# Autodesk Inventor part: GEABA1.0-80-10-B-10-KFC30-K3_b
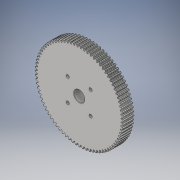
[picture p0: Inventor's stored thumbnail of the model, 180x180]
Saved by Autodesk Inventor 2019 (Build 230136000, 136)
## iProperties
Created: 2022-11
Part Number: GEABA1.0-80-10-B-10-KFC30-K3_b
Material: Generic
Catalog Web Link: www.cadenas.de
Description: GEABM, GEABMS, GEABMT, GEABP, GEABPS, GEABPT, GEABA, GEABAS, GEABAT_body-Plastic Spur Gears - Pressure Angle 20 Degrees, Module 0.5/0.8/1.0/1.5/2.0/2.5/3.0
Vendor: MISUMI
Document SubType Name: Modeling
Designer: psAdmin
Manufacturer: MISUMI
Mass: 60.3274 g
Surface Area: 174.386 cm^2
Volume: 60.3274 cm^3
Density: 1 g/cm^3
Appearance: PSOLRGB-175-175-175
Category: PARTsolutions
Company: MISUMI
Title: GEABA1.0-80-10-B-10-KFC30-K3
Author: Cadenas PARTsolutions
Comments: Plastic Spur Gears - Pressure Angle 20 Degrees, Module 0.5/0.8/1.0/1.5/2.0/2.5/3.0
PSOL_IDENT_0: {$CADENAS_DATA/23d-libs/misumi/metric/54_spur_gears/geabms20/geabms20.prj},408 {VTYP=3D},{NB=GEABA1.
PSOL_IDENT_1: 0-80-10-B-10-KFC30-K3_b},{LINA=GEABA1.0-80-10-B-10-KFC30-K3},{NN=GEABM, GEABMS, GEABMT, GEABP, GEABP
PSOL_IDENT_2: S, GEABPT, GEABA, GEABAS, GEABAT_body},{DATE=17.10.2022 23:48:33},{GEOMDATE=14.09.2022 05:11:00},{VE
PSOL_IDENT_3: RSION=},{LINEID=30},{WBVAR=MATSG,MATCR,NT,B,TS,PS,ALT1,ALT2,TPC,ALT11,ALT10,BS,ALT3,Z,J,ALT4,Q,R,S,T
PSOL_IDENT_4: ,ALT5,LFC,LTC,MALT5,ALT6,KFC,KTC,K},{WBNUMERIC=NT,B,BS,Z,J,Q,R,S,T,LFC,LTC,KFC,KTC,K}  {NB=GEABA1.0-
PSOL_IDENT_5: 80-10-B-10-KFC30-K3_b},{LINA=GEABA1.0-80-10-B-10-KFC30-K3},{KT=DUMMY},{PN=GEABA1.0-80-10-B-10-KFC30-
PSOL_IDENT_6: K3},{TYPE=GEABA},{MATSG=PB},{MATSGALG='MCN','MC Nylon','PW','Polyacetal White','PB','Polyacetal Blue'
PSOL_IDENT_7: },{MATCR=},{MATCRALG='','-','S45C','1045 Carbon Steel','SUS304','304 Stainless Steel'},{MOD=1.0},{MO
PSOL_IDENT_8: D1=1.0},{NT=80},{NTALG=15,16,18,20,22,24,25,26,28,30,32,35,36,40,45,48,50,55,60,70,75,80,90,100,120}
PSOL_IDENT_9: ,{B=10},{BALG=10,15},{TS=B},{TSALG='A','A','B','B'},{TSPN=-B},{PS=10},{PSALG='10','10','11','11','12'
PSOL_IDENT_10: ,'12','13','13','14','14','15','15','16','16','17','17','18','18','19','19','20','20','21','21','22'
PSOL_IDENT_11: ,'22','23','23','24','24','25','25','26','26','27','27','28','28'},{PSCRL='10','10','11','11','12','
PSOL_IDENT_12: 12','13','13','14','14','15','15','16','16','17','17','18','18','19','19','20','20','21','21','22','
PSOL_IDENT_13: 22','23','23','24','24','25','25','26','26','27','27','28','28'},{PSCRW='10','10','12','12','15','15'
PSOL_IDENT_14: ,'20','20'},{DD=80.0},{DD05=40},{DD08=64},{DD10=80},{DD15=120},{DD20=0},{DD25=0},{DD30=0},{D=82.0},{
PSOL_IDENT_15: D05=41},{D08=65.6},{D10=82},{D15=123},{D20=0},{D25=0},{D30=0},{G=77.50},{G05=38.75},{G08=62},{G10=77
PSOL_IDENT_16: .5},{G15=116.25},{G20=0},{G25=0},{G30=0},{H=40.0},{L=20},{LL1=10},{LL2=4.0},{M=M4},{M3D=4},{P=10.00}
PSOL_IDENT_17: ,{DD1=0},{CIFR=15},{CIFM=4},{CIFK=0},{CIFTAP=1},{ALT1=},{ALT1ALG='','w/o Set Screw','KC90','with KC9
PSOL_IDENT_18: 0 (Set Screw)','KC120','with KC120 (Set Screw)'},{ALT1PN=},{ALT2=},{ALT2ALG='','w/o TPC (Tapped Hole
PSOL_IDENT_19: Dimension)','TPC','with TPC (Tapped Hole Dimension)'},{TPC=N/A},{TPCALG='N/A'},{ALT2PN=},{KC=0},{AL
PSOL_IDENT_20: T11=},{ALT11ALG='', 'w/o GBA (Gear bottom adjustment of phase focus)', 'GBA', 'with GBA (Gear bottom
PSOL_IDENT_21: adjustment of phase focus)' },{ALT11PN=},{DEG=0},{ALT10=},{ALT10ALG= '','w/o BS (Boss Cut)','BS','w
PSOL_IDENT_22: ith BS (Boss Cut)' },{ALT10PN=},{BS=0.0},{BSALG=0},{BSMIN=7},{BSMINALG=7.000},{BSMAX=10},{LL13D=10},
PSOL_IDENT_23: {LL23D=16},{LBS=20},{ALT3=},{ALT3ALG= '','w/o Stepped Hole','DHL','with DHL (Stepped Hole)','DHR','w
PSOL_IDENT_24: ith DHR (Stepped Hole)' },{ALT3PN=},{ZJPN=},{ALT31=1},{ALT32=1},{Z=0},{ZALG=0},{ZMINL=12},{ZMAXL=73}
PSOL_IDENT_25: ,{ZMINR=12},{ZMAXR=36},{ZPN=},{J=0.0},{JALG=0},{JMIN=2},{JMAX=0},{JPN=},{ALT4=},{ALT4ALG= '','w/o WD
PSOL_IDENT_26: H (Both Ends Stepped Hole)','WDH','with WDH (Both Ends Stepped Hole)' },{ALT4PN=},{QRSTPN=},{LB=20.0
PSOL_IDENT_27: 00},{Q=0},{QALG=0},{QMIN=12},{QMAX=36},{QPN=},{R=0},{RALG=0},{RMIN=12},{RMAX=36},{RPN=},{S=0},{SALG=
PSOL_IDENT_28: 0},{SMIN=3},{SMAX=14},{SPN=},{T=0},{TALG=0},{TMIN=3},{TMAX=0},{TPN=},{ALT5=},{ALT5ALG= '','Not appli
PSOL_IDENT_29: cable' },{LFC=0},{LFCALG=0},{LTC=0},{LTCALG=0},{LPCDMIN=18},{LPCDMAX=70},{LCMAX=73},{MALT5=N/A},{MAL
PSOL_IDENT_30: T5ALG= 'N/A' },{LCMAX2=70},{C=0.0},{ALT5PN=},{ALT6=KFC},{ALT6ALG= '','w/o Side Through Hole','KFC','
PSOL_IDENT_31: with KFC (Side Through Hole)','KTC','with KTC (Side Through Hole)' },{ALT6PN=-KFC},{KFTCPN=30-K3},{K
PSOL_IDENT_32: FC=30},{KFCALG=[17:33/1],[47:70/1]},{KFCPN=30},{KTC=0},{KTCALG=[0]},{KTCPN=},{KPCDMIN1=17},{KPCDMAX1=
PSOL_IDENT_33: 33},{KPCDMIN2=47},{KPCDMAX2=70},{K=3.0},{KALG=[3:6/0.5]},{KPCD=30},{KPN=-K3},{SCREW=4},{SCREWL=3},{A
PSOL_IDENT_34: G=0},{PCD=30},{SHN=4},{SHDEG1=45},{SHDEG2=90},{PZQRDD2=10},{D1=1.125},{D2=2.25},{D3=20},{D4=0.1},{D5=
PSOL_IDENT_35: 13.333333},{D6=12.307692},{D7=0.85},{D8=0.5},{D9=0.829978},{S1=15},{S2=0.5},{KR=15}
NB: GEABA1.0-80-10-B-10-KFC30-K3_b
NN: GEABM, GEABMS, GEABMT, GEABP, GEABPS, GEABPT, GEABA, GEABAS, GEABAT_body
NT: 80
NBSYN: $PN._b
LINA: GEABA1.0-80-10-B-10-KFC30-K3
CATALOG: Misumi
PN: GEABA1.0-80-10-B-10-KFC30-K3
MATSG: Polyacetal Blue
MATCR: -
MOD: 1.0
B: 10
TS: B
PS: 10
DD: 80
D: 82
G: 77.5
H: 40
L: 20
LL1: 10
LL2: 4
M: M4
DD1: 0
ALT1: w/o Set Screw
ALT2: w/o TPC (Tapped Hole Dimension)
TPC: N/A
ALT11: w/o GBA (Gear bottom adjustment of phase focus)
ALT10: w/o BS (Boss Cut)
BS: 0
ALT3: w/o Stepped Hole
Z: 0
J: 0
ALT4: w/o WDH (Both Ends Stepped Hole)
Q: 0
R: 0
S: 0
T: 0
ALT5: Not applicable
LFC: 0
LTC: 0
MALT5: N/A
C: 0
ALT6: with KFC (Side Through Hole)
KFC: 30
KTC: 0
K: 3
SUPPLIER: MISUMI
ARTICLENO: GEABA1.0-80-10-B-10-KFC30-K3_b
BOMINFO: GEABA1.0-80-10-B-10-KFC30-K3
CREATOR: CADENAS GmbH
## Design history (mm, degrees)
sketch "Sketch_2"
  geometry: L1 (0, -500)-(0, 500); L2 (0, 0)-(40.5, 0); L3 (40.5, 0)-(43, -0.67); L4 (43, -0.67)-(43, -9.33); L5 (43, -9.33)-(40.5, -10); L6 (40.5, -10)-(20, -10); L7 (20, -10)-(20, -19.7); L8 (20, -19.7)-(19.7, -20); L9 (19.7, -20)-(0, -20); L10 (0, -20)-(0, 0)
  constraints: 20 end point
revolve "Revolution1" sketch "Sketch_2" stored, may be unused: angle "d0" = 360 deg
sketch "_____12"
  geometry: C1 r 164 at (0, 0); A1 r 41 centre (0, 0) between (-40.999, 0.33) and (-40.999, -0.33); A2 r 0.1 centre (-40.899, -0.329) between (-40.999, -0.33) and (-40.938, -0.421); A3 r 13.333 centre (-35.679, 11.831) between (-40.938, -0.421) and (-39.992, -0.785); A4 r 0.83 centre (-39.724, 0) between (-39.992, -0.785) and (-39.882, -0.815); A5 r 12.308 centre (-42.24, -12.894) between (-39.094, -0.996) and (-39.882, -0.815); A6 r 0.5 centre (-39.222, -1.479) between (-38.722, -1.46) and (-39.094, -0.996); A7 r 38.75 centre (0, 0) between (-38.722, -1.46) and (-38.718, -1.583); A8 r 0.5 centre (-39.217, -1.603) between (-39.052, -2.075) and (-38.718, -1.583); A9 r 12.308 centre (-43.122, 9.541) between (-39.823, -2.317) and (-39.052, -2.075); A10 r 0.83 centre (-39.601, -3.117) between (-39.823, -2.317) and (-39.931, -2.355); A11 r 13.333 centre (-34.641, -14.594) between (-39.931, -2.355) and (-40.845, -2.792); A12 r 0.1 centre (-40.798, -2.881) between (-40.845, -2.792) and (-40.898, -2.888); A13 r 41 centre (0, 0) between (-40.898, -2.888) and (-40.846, -3.546); A14 r 0.1 centre (-40.747, -3.537) between (-40.846, -3.546) and (-40.779, -3.632); A15 r 13.333 centre (-36.497, 8.995) between (-40.779, -3.632) and (-39.807, -3.921); A16 r 0.83 centre (-39.601, -3.117) between (-39.807, -3.921) and (-39.695, -3.941); A17 r 12.308 centre (-41.098, -16.169) between (-38.896, -4.06) and (-39.695, -3.941); A18 r 0.5 centre (-38.985, -4.552) between (-38.489, -4.494) and (-38.896, -4.06); A19 r 38.75 centre (0, 0) between (-38.489, -4.494) and (-38.474, -4.615); A20 r 0.5 centre (-38.971, -4.675) between (-38.769, -5.132) and (-38.474, -4.615); A21 r 12.308 centre (-43.737, 6.128) between (-39.518, -5.434) and (-38.769, -5.132); A22 r 0.83 centre (-39.235, -6.214) between (-39.518, -5.434) and (-39.623, -5.48); A23 r 13.333 centre (-33.389, -17.267) between (-39.623, -5.48) and (-40.5, -5.988); A24 r 0.1 centre (-40.447, -6.073) between (-40.5, -5.988) and (-40.546, -6.087); A25 r 41 centre (0, 0) between (-40.546, -6.087) and (-40.442, -6.74); A26 r 0.1 centre (-40.344, -6.723) between (-40.442, -6.74) and (-40.368, -6.82); A27 r 13.333 centre (-37.09, 6.104) between (-40.368, -6.82) and (-39.377, -7.032); A28 r 0.83 centre (-39.235, -6.214) between (-39.377, -7.032) and (-39.263, -7.044); A29 r 12.308 centre (-39.703, -19.343) between (-38.457, -7.099) and (-39.263, -7.044); A30 r 0.5 centre (-38.508, -7.596) between (-38.017, -7.5) and (-38.457, -7.099); A31 r 38.75 centre (0, 0) between (-38.017, -7.5) and (-37.993, -7.62); A32 r 0.5 centre (-38.484, -7.718) between (-38.247, -8.158) and (-37.993, -7.62); A33 r 12.308 centre (-44.083, 2.677) between (-38.97, -8.518) and (-38.247, -8.158); A34 r 0.83 centre (-38.626, -9.273) between (-38.97, -8.518) and (-39.071, -8.572); A35 r 13.333 centre (-31.931, -19.833) between (-39.071, -8.572) and (-39.905, -9.147); A36 r 0.1 centre (-39.846, -9.227) between (-39.905, -9.147) and (-39.943, -9.25); A37 r 41 centre (0, 0) between (-39.943, -9.25) and (-39.789, -9.892); A38 r 0.1 centre (-39.692, -9.868) between (-39.789, -9.892) and (-39.709, -9.966); A39 r 13.333 centre (-37.455, 3.175) between (-39.709, -9.966) and (-38.704, -10.1); A40 r 0.83 centre (-38.626, -9.273) between (-38.704, -10.1) and (-38.59, -10.103); A41 r 12.308 centre (-38.063, -22.399) between (-37.782, -10.094) and (-38.59, -10.103); A42 r 0.5 centre (-37.793, -10.594) between (-37.312, -10.459) and (-37.782, -10.094); A43 r 38.75 centre (0, 0) between (-37.312, -10.459) and (-37.278, -10.577); A44 r 0.5 centre (-37.759, -10.714) between (-37.489, -11.134) and (-37.278, -10.577); A45 r 12.308 centre (-44.157, -0.79) between (-38.182, -11.549) and (-37.489, -11.134); A46 r 0.83 centre (-37.78, -12.275) between (-38.182, -11.549) and (-38.278, -11.611); A47 r 13.333 centre (-30.277, -22.277) between (-38.278, -11.611) and (-39.065, -12.25); A48 r 0.1 centre (-38.999, -12.325) between (-39.065, -12.25) and (-39.094, -12.355); A49 r 41 centre (0, 0) between (-39.094, -12.355) and (-38.89, -12.983); A50 r 0.1 centre (-38.795, -12.952) between (-38.89, -12.983) and (-38.804, -13.051); A51 r 13.333 centre (-37.589, 0.227) between (-38.804, -13.051) and (-37.792, -13.105); A52 r 0.83 centre (-37.78, -12.275) between (-37.792, -13.105) and (-37.678, -13.099); A53 r 12.308 centre (-36.188, -25.316) between (-36.873, -13.028) and (-37.678, -13.099); A54 r 0.5 centre (-36.845, -13.527) between (-36.376, -13.355) and (-36.873, -13.028); A55 r 38.75 centre (0, 0) between (-36.376, -13.355) and (-36.334, -13.469); A56 r 0.5 centre (-36.802, -13.643) between (-36.499, -14.041) and (-36.334, -13.469); A57 r 12.308 centre (-43.959, -4.252) between (-37.158, -14.509) and (-36.499, -14.041); A58 r 0.83 centre (-36.7, -15.202) between (-37.158, -14.509) and (-37.249, -14.579); A59 r 13.333 centre (-28.435, -24.584) between (-37.249, -14.579) and (-37.983, -15.277); A60 r 0.1 centre (-37.911, -15.347) between (-37.983, -15.277) and (-38.004, -15.384); A61 r 41 centre (0, 0) between (-38.004, -15.384) and (-37.751, -15.995); A62 r 0.1 centre (-37.659, -15.956) between (-37.751, -15.995) and (-37.661, -16.056); A63 r 13.333 centre (-37.491, -2.723) between (-37.661, -16.056) and (-36.648, -16.03); A64 r 0.83 centre (-36.7, -15.202) between (-36.648, -16.03) and (-36.534, -16.015)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; 1 further point
  constraints: 1920 point on circle, 961 centre point
extrude "Extrusion1" cut sketch "_____12" distance "d1" = 10; taper "d2" = 0 deg
sketch "Sketch3"
  geometry: 1 further point
hole "Hole1" sketch "Sketch3" at (0, 0) diameter "d3" = 10; stored, may be unused: countersink angle "d7" = 90 deg, drill point angle "d9" = 0 deg; dims "d4" = 6, "d5" = 4, "d6" = 2, "d8" = 20
sketch "_____5"
  geometry: L1 (500, 0)-(-500, 0); L2 (19.7, 5)-(20, 5); L3 (20, 5)-(20, 5.3); L4 (20, 5.3)-(19.7, 5)
  constraints: 8 end point
revolve "Revolution2" sketch "_____5" stored, may be unused: angle "d10" = 360 deg
sketch "_____13"
  geometry: L1 (500, 0)-(-500, 0); L2 (0, 5.3)-(0, 5); L3 (0, 5)-(0.3, 5); L4 (0.3, 5)-(0, 5.3)
  constraints: 8 end point
revolve "Revolution3" sketch "_____13" stored, may be unused: angle "d11" = 360 deg
sketch "Sketch_4"
  geometry: L1 (0, 20)-(0, 0); L2 (0, 0)-(-1.621, 0); L3 (-1.621, 0)-(-1.621, 19.621); L4 (-1.621, 19.621)-(-2, 20); L5 (-2, 20)-(0, 20); L6 (0, 20)-(0, 0)
  constraints: 12 end point
revolve "Revolution4" sketch "Sketch_4" stored, may be unused: angle "d12" = 360 deg
thread "Thread1" dims "d13" = 14.621, "d14" = 0
sketch "Sketch7"
  geometry: 1 further point
hole "Hole2" sketch "Sketch7" at (-10.607, 10.607) diameter "d15" = 3; stored, may be unused: countersink angle "d19" = 90 deg, drill point angle "d21" = 0 deg; dims "d16" = 6, "d17" = 4, "d18" = 2, "d20" = 20
pattern_linear "Rectangular Pattern1" dims "d24" = 21.2132, "d27" = 21.2132
node "gear_to_screw_XY"
node "gear_to_screw_YZ"
node "gear_to_screw_ZX"
node "gear_to_screw_X"
node "gear_to_screw_Y"
node "gear_to_screw_Z"
node "gear_to_screw_Center"
body "Solid1"
